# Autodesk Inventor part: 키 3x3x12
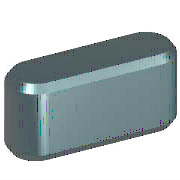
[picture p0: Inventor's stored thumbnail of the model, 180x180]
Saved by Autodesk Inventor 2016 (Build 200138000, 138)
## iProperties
Created: 2012-02
Part Number: 키 3x3x12
Material: 강철, 연강
Description: 키 및 해당 키홈
Document SubType Name: Modeling
Standard: KS B 1311
Designer: mduedu
Standards Organization: KS
Language: ko-KR
Size Designation: 3 x 3 x 12
Categories: <MemberInstance><Categories><Category DisplayName="샤프트 부품" InternalName="7f7aeb1f-a693-4053-b835-cee3144e0d98" Mnemonic="SHFT"><Category DisplayName="키" Interna
Density: 1 g/cm^3
Appearance: 노란색
IsCustomPart: 1
Author: mduedu
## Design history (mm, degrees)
workplane "Work Plane1"
workplane "Work Plane2"
sketch "스케치1"
  geometry: L1 (1.5, 1.5)-(10.5, 1.5); L2 (10.5, -1.5)-(1.5, -1.5); L3 (0, 9.4)-(0, -7.4) reference; L4 (-5, 0)-(30, 0) reference; L5 (12, 0)-(12, 7); A1 r 1.5 centre (1.5, 0) between (1.5, 1.5) and (1.5, -1.5); A2 r 1.5 centre (10.5, 0) between (10.5, -1.5) and (10.5, 1.5)
  constraints: 6 end point, 5 point on circle, 4 tangent, 3 point on line, 2 centre point, 1 horizontal, 1 parallel, 1 perpendicular
  dimensions: "d0" = 1.5 radius of A1 (= 0.5 x PB); "d13" = 1.5 radius of A2 (= 0.5 x PB); "d14" = 12 distance between parallel lines of L5 L3 (= NLG)
extrude "본체1" new body sketch "스케치1" taper "d3" = 0 deg; stored distance "d4" = 10
workplane "Work Plane3"
body "Solid1"
chamfer "모따기1" distance "d8" = 0.25 (= PHH); stored, may be unused: second distance "d9" = 0.25 (= PHH), angle "d15" = 45 deg
other parameters: "d1" = -1.8 (= -PNT), "d2" = 1.2 (= PH - PNT), "NLG" = 12 [user parameter; used in 3 equation terms], "PB" = 3 [user parameter; used in 2 equation terms], "PNT" = 1.8 [user parameter; used in 2 equation terms], "PH" = 3 [user parameter; used in 1 equation term], "PHH" = 0.25 [user parameter; used in 2 equation terms], "d10" = 0, "d16" = 0, "d17" = 0, "d18" = 0, "WDMIN" = 8 [user parameter], "PLB2" = 12 (= NLG) [user parameter], "PLB1" = 12 (= NLG) [user parameter], "RR" = 0.08 [user parameter], "PUEB" = 1.4 [user parameter]
